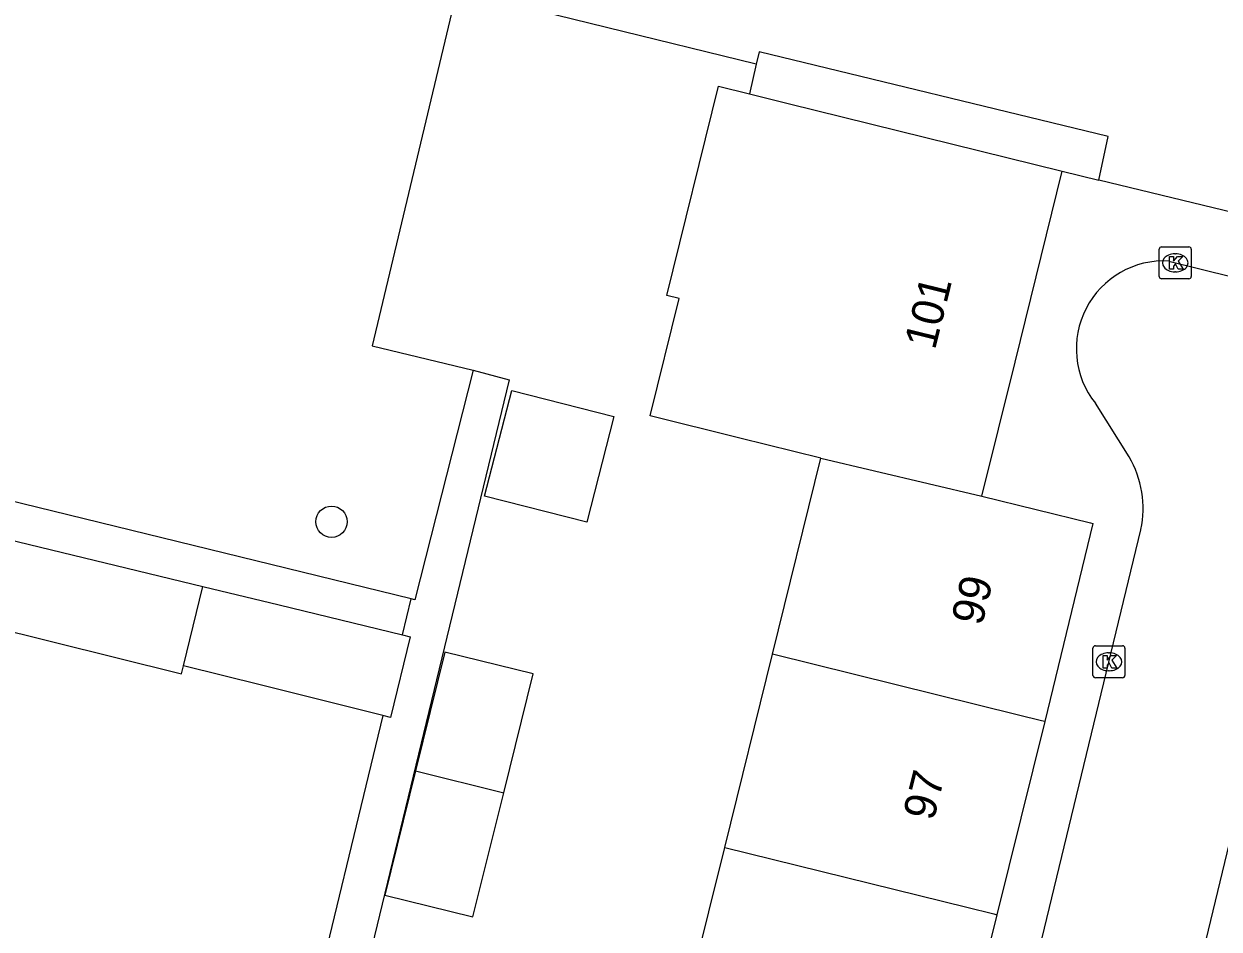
# Model space of a CAD drawing. Extents: x 162812 to 163818, y 381639 to 382470.
# Drawn here: x 163388.73 to 163426.12, y 382330.99 to 382359.3 of the extents above; entities that cross this region are included whole.
import ezdxf

# ---------------------------------------------------------------- set-up
doc = ezdxf.new("R2010")
doc.units = 0
for name, color, linetype in [('IMGEO_Boom', 7, 'Continuous'), ('IMGEO_Kolk', 7, 'Continuous'), ('IMGEO_Loofbos', 7, 'Continuous'), ('IMGEO_Pand', 7, 'Continuous'), ('IMGEO_Pand_nummerreeks', 7, 'Continuous'), ('IMGEO_Rijbaan_lokaal_open', 7, 'Continuous'), ('IMGEO_Voetpad_open', 7, 'Continuous')]:
    doc.layers.add(name, color=color, linetype=linetype)

msp = doc.modelspace()

# ---------------------------------------------------------------- linework, layer by layer
at = {"layer": 'IMGEO_Boom'}
msp.add_circle((163398.35, 382343.729), 0.489, dxfattribs=at)
at = {"layer": 'IMGEO_Kolk'}
for p, q in [((163424.246, 382351.4), (163424.246, 382352.252)), ((163424.321, 382352.326), (163425.173, 382352.326)), ((163425.247, 382352.252), (163425.247, 382351.4)), ((163424.734, 382352.106), (163424.759, 382352.106)), ((163424.757, 382351.546), (163424.732, 382351.546)), ((163425.173, 382351.326), (163424.321, 382351.326)), ((163422.173, 382338.922), (163422.173, 382339.774)), ((163422.248, 382339.848), (163423.1, 382339.848)), ((163422.661, 382339.628), (163422.686, 382339.628)), ((163423.174, 382339.774), (163423.174, 382338.922)), ((163423.1, 382338.848), (163422.248, 382338.848)), ((163422.684, 382339.068), (163422.659, 382339.068))]:
    msp.add_line(p, q, dxfattribs=at)
for points in [[(163424.246, 382351.4), (163424.246, 382352.252)], [(163424.321, 382352.326), (163425.173, 382352.326)], [(163425.247, 382352.252), (163425.247, 382351.4)], [(163424.567, 382352.026), (163424.69, 382352.026), (163424.69, 382351.875), (163424.82, 382352.026), (163424.984, 382352.026), (163424.838, 382351.875), (163424.991, 382351.626), (163424.839, 382351.626), (163424.754, 382351.79), (163424.69, 382351.723), (163424.69, 382351.626), (163424.567, 382351.626), (163424.567, 382352.026)], [(163425.173, 382351.326), (163424.321, 382351.326)], [(163422.173, 382338.922), (163422.173, 382339.774)], [(163422.248, 382339.848), (163423.1, 382339.848)], [(163422.494, 382339.548), (163422.617, 382339.548), (163422.617, 382339.397), (163422.747, 382339.548), (163422.911, 382339.548), (163422.765, 382339.397), (163422.918, 382339.148), (163422.766, 382339.148), (163422.681, 382339.312), (163422.617, 382339.245), (163422.617, 382339.148), (163422.494, 382339.148), (163422.494, 382339.548)], [(163423.174, 382339.774), (163423.174, 382338.922)], [(163423.1, 382338.848), (163422.248, 382338.848)]]:
    msp.add_lwpolyline(points, dxfattribs=at)
for centre, start, end in [((163424.323, 382352.25), 91.552, 178.448), ((163424.323, 382352.25), 91.552, 178.448), ((163425.171, 382352.25), 1.552, 88.448), ((163425.171, 382352.25), 1.552, 88.448), ((163424.323, 382351.402), 181.552, 268.448), ((163424.323, 382351.402), 181.552, 268.448), ((163425.171, 382351.402), 271.552, 358.448), ((163425.171, 382351.402), 271.552, 358.448), ((163422.25, 382339.772), 91.552, 178.448), ((163422.25, 382339.772), 91.552, 178.448), ((163423.098, 382339.772), 1.552, 88.448), ((163423.098, 382339.772), 1.552, 88.448), ((163422.25, 382338.924), 181.552, 268.448), ((163422.25, 382338.924), 181.552, 268.448), ((163423.098, 382338.924), 271.552, 358.448), ((163423.098, 382338.924), 271.552, 358.448)]:
    msp.add_arc(centre, 0.0765, start, end, dxfattribs=at)
for centre, major_axis, ratio, start_param, end_param in [((163424.733, 382351.826), (-0.387, 0.002), 0.722429, 4.712389, 7.853982), ((163424.758, 382351.826), (-0.39, 0.002), 0.717154, 1.570796, 4.712389), ((163422.66, 382339.348), (-0.387, 0.002), 0.722429, 4.712389, 7.853982), ((163422.685, 382339.348), (-0.39, 0.002), 0.717154, 1.570796, 4.712389)]:
    msp.add_ellipse(centre, major_axis=major_axis, ratio=ratio, start_param=start_param, end_param=end_param, dxfattribs=at)
at = {"layer": 'IMGEO_Loofbos'}
msp.add_lwpolyline([(163411.637, 382358.041), (163402.273, 382360.348), (163399.618, 382349.231), (163402.78, 382348.474)], dxfattribs=at)
at = {"layer": 'IMGEO_Pand'}
for points in [[(163413.663, 382345.719), (163411.128, 382346.346), (163408.318, 382347.041), (163409.225, 382350.71), (163408.844, 382350.804), (163410.462, 382357.349), (163411.425, 382357.111)], [(163411.425, 382357.111), (163412.638, 382356.811), (163421.214, 382354.69)], [(163418.7, 382344.531), (163419.736, 382348.718), (163421.214, 382354.69)], [(163403.138, 382344.529), (163403.986, 382347.838), (163407.182, 382347.019), (163406.333, 382343.71), (163403.138, 382344.529)], [(163412.145, 382339.584), (163413.663, 382345.719)], [(163413.663, 382345.719), (163418.7, 382344.531)], [(163418.7, 382344.531), (163422.096, 382343.691), (163422.17, 382343.676), (163420.665, 382337.477)], [(163388.214, 382343.18), (163394.322, 382341.702)], [(163393.722, 382339.222), (163394.322, 382341.702)], [(163394.322, 382341.702), (163396.707, 382341.125), (163400.566, 382340.191)], [(163387.562, 382340.485), (163393.66, 382338.967), (163393.722, 382339.222)], [(163400.566, 382340.191), (163400.806, 382340.133), (163400.196, 382337.608), (163399.957, 382337.668)], [(163403.737, 382335.252), (163404.656, 382338.967), (163401.898, 382339.649), (163400.979, 382335.934)], [(163410.651, 382333.542), (163412.145, 382339.584)], [(163420.665, 382337.477), (163420.565, 382337.502), (163419.848, 382337.679), (163412.145, 382339.584)], [(163399.957, 382337.668), (163396.163, 382338.613), (163393.722, 382339.222)], [(163420.665, 382337.477), (163419.17, 382331.435)], [(163400.979, 382335.934), (163400.019, 382332.053), (163402.776, 382331.37), (163403.737, 382335.252)], [(163400.979, 382335.934), (163403.737, 382335.252)], [(163409.157, 382327.501), (163410.651, 382333.542)], [(163410.651, 382333.542), (163418.229, 382331.668), (163419.07, 382331.46), (163419.17, 382331.435)], [(163419.17, 382331.435), (163417.675, 382325.393)]]:
    msp.add_lwpolyline(points, dxfattribs=at)
at = {"layer": 'IMGEO_Rijbaan_lokaal_open'}
for points in [[(163424.548, 382351.882), (163444.241, 382347.005), (163444.389, 382346.827)], [(163423.304, 382345.757), (163422.25, 382347.432)], [(163416.785, 382315.02), (163423.67, 382343.48)], [(163427.647, 382338.711), (163426.87, 382335.489), (163422.441, 382317.129), (163421.662, 382313.876)]]:
    msp.add_lwpolyline(points, dxfattribs=at)
for centre, radius, start, end in [((163424.396, 382349.142), 2.744, 86.8326, 218.5434), ((163420.566, 382344.149), 3.175, 347.839, 30.424)]:
    msp.add_arc(centre, radius, start, end, dxfattribs=at)
at = {"layer": 'IMGEO_Voetpad_open'}
for points in [[(163400.84, 382341.313), (163357.479, 382351.919), (163359.169, 382358.841)], [(163422.352, 382354.415), (163422.648, 382355.78), (163411.726, 382358.429), (163411.637, 382358.041)], [(163411.637, 382358.041), (163411.425, 382357.111)], [(163421.214, 382354.69), (163422.352, 382354.415)], [(163447.401, 382348.351), (163422.352, 382354.415)], [(163402.78, 382348.474), (163403.912, 382348.17), (163398.883, 382327.418), (163398.019, 382323.845), (163397.167, 382320.322), (163395.918, 382315.172)], [(163402.78, 382348.474), (163400.952, 382341.286), (163400.84, 382341.313)], [(163400.566, 382340.191), (163400.84, 382341.313)], [(163399.957, 382337.668), (163397.53, 382327.615)]]:
    msp.add_lwpolyline(points, dxfattribs=at)

# ---------------------------------------------------------------- texts
at = {"layer": 'IMGEO_Pand_nummerreeks'}
for s, rotation, p in [('101', 76.1003, (163417.229, 382349.077)), ('99', 76.106, (163418.696, 382340.444)), ('97', 76.106, (163417.187, 382334.344))]:
    msp.add_text(s, height=1, rotation=rotation, dxfattribs=at).set_placement(p)

doc.saveas('drawing.dxf')
